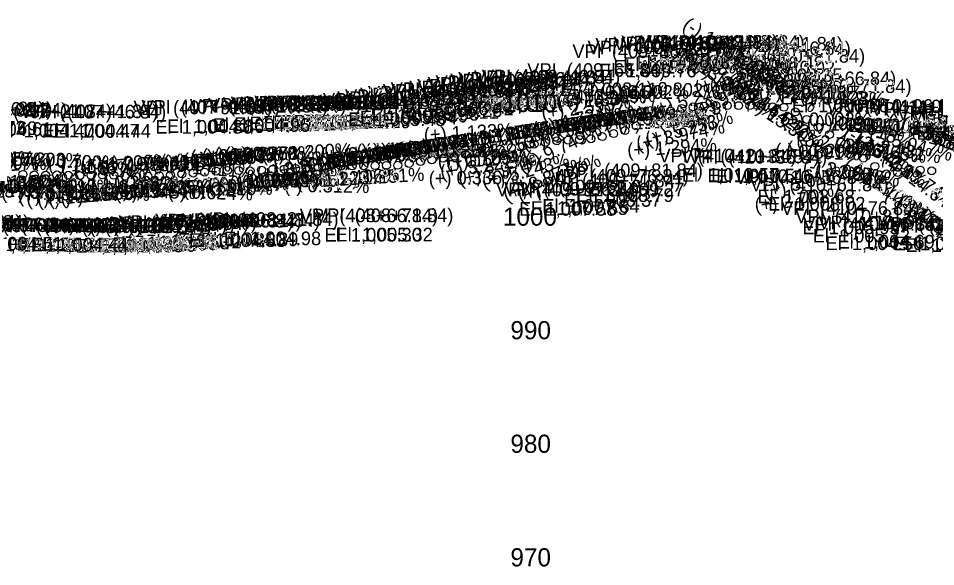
# Model space of a CAD drawing. Extents: x 16972137 to 16976972, y 12558490 to 12559551.
# Drawn here: x 16975097.7 to 16975501.5, y 12558789.2 to 12559030.6 of the extents above; entities that cross this region are included whole.
import ezdxf

# ---------------------------------------------------------------- set-up
doc = ezdxf.new("R2010")
doc.units = 0
for name, color, linetype in [('RD_DDB_ElevTX', 7, 'Continuous'), ('RD_DDB_GradeTX', 7, 'Continuous'), ('RD_DDB_PI', 7, 'Continuous')]:
    doc.layers.add(name, color=color, linetype=linetype)

msp = doc.modelspace()

# ---------------------------------------------------------------- linework, layer by layer
at = {"layer": 'RD_DDB_PI'}
for centre in [(16975399.74, 12558991.93), (16975404.74, 12558992.17), (16975409.74, 12558992.19), (16975414.74, 12558992.16), (16975419.74, 12558992.16), (16975424.74, 12558991.88), (16975379.74, 12558988.12), (16975384.74, 12558989.77), (16975389.74, 12558990.95), (16975394.74, 12558991.6), (16975429.74, 12558991.62), (16975434.74, 12558991.42), (16975439.74, 12558989.42), (16975374.74, 12558985.68), (16975444.74, 12558986.08), (16975359.74, 12558979.85), (16975364.74, 12558981.16), (16975369.74, 12558983.25), (16975449.74, 12558982.72), (16975329.74, 12558975.94), (16975334.74, 12558976.66), (16975339.74, 12558976.94), (16975344.74, 12558977.21), (16975349.74, 12558977.54), (16975354.74, 12558978.53), (16975454.74, 12558979.44), (16975459.74, 12558976.17), (16975304.74, 12558972.17), (16975309.74, 12558972.94), (16975314.74, 12558973.7), (16975319.74, 12558974.45), (16975324.74, 12558975.2), (16975464.74, 12558972.74), (16975274.74, 12558967.5), (16975279.74, 12558968.29), (16975284.74, 12558969.08), (16975289.74, 12558969.86), (16975294.74, 12558970.63), (16975299.74, 12558971.41), (16975469.74, 12558969.07), (16975189.74, 12558963.63), (16975194.74, 12558963.55), (16975199.74, 12558963.47), (16975204.74, 12558963.78), (16975209.74, 12558964.13), (16975214.74, 12558964.23), (16975219.74, 12558964.55), (16975224.74, 12558964.83), (16975229.74, 12558965.11), (16975234.74, 12558965.36), (16975239.74, 12558965.51), (16975244.74, 12558965.61), (16975249.74, 12558965.68), (16975254.74, 12558965.75), (16975259.74, 12558965.82), (16975264.74, 12558965.9), (16975269.74, 12558966.7), (16975474.74, 12558965.41), (16975489.74, 12558964.02), (16975494.74, 12558963.79), (16975499.74, 12558963.47), (16975099.74, 12558961.88), (16975104.74, 12558961.64), (16975109.74, 12558961.56), (16975114.74, 12558961.68), (16975119.74, 12558961.53), (16975124.74, 12558961.39), (16975129.74, 12558961.5), (16975134.74, 12558961.65), (16975139.74, 12558961.51), (16975144.74, 12558961.16), (16975149.74, 12558961), (16975154.74, 12558961.08), (16975159.74, 12558961.31), (16975164.74, 12558961.66), (16975169.74, 12558962.07), (16975174.74, 12558962.48), (16975179.74, 12558962.9), (16975184.74, 12558963.33), (16975479.74, 12558962.09), (16975484.74, 12558962.76)]:
    msp.add_circle(centre, 1.75, dxfattribs=at)

# ---------------------------------------------------------------- texts
at = {"layer": 'RD_DDB_ElevTX'}
for s, p in [('1010', (16975311.02, 12558989.31)), ('1000', (16975311.02, 12558939.31)), ('990', (16975314.32, 12558889.31)), ('980', (16975314.32, 12558839.31)), ('970', (16975314.32, 12558789.31))]:
    msp.add_text(s, height=8, dxfattribs=at).set_placement(p)
at = {"layer": 'RD_DDB_GradeTX'}
for s, rotation, p in [('(-) 13.342%', 326.2932, (16975389.68, 12559026.42)), ('(-) 8.018%', 338.1532, (16975381.13, 12559016.15)), ('(-) 13.063%', 326.8491, (16975404.49, 12559015.84)), ('(-) 13.453%', 326.0724, (16975388.24, 12559013.24)), ('(+) 6.582%', 18.2168, (16975396.62, 12558996.84)), ('(-) 13.741%', 325.5091, (16975412.28, 12559012.42)), ('(-) 13.124%', 326.7268, (16975394.42, 12559008.25)), ('(+) 4.734%', 13.3166, (16975402.77, 12558997.12)), ('(+) 9.749%', 25.9875, (16975396.34, 12558986.2)), ('(+) 2.593%', 7.3885, (16975407.67, 12558996.3)), ('(-) 14.642%', 323.7924, (16975410.07, 12559001.6)), ('(-) 0.802%', 357.7037, (16975368.67, 12558997.07)), ('(+) 5.243%', 14.6898, (16975376.84, 12558987.43)), ('(+) 9.735%', 25.955, (16975390.76, 12558983.47)), ('(+) 1.334%', 3.8169, (16975414.67, 12558995.94)), ('(-) 14.642%', 323.7924, (16975415.07, 12558997.94)), ('(+) 0.965%', 2.763, (16975418.69, 12558995.85)), ('(+) 0.065%', 0.1852, (16975423.73, 12558995.23)), ('(+) 1.334%', 3.8169, (16975334.86, 12558990.61)), ('(+) 0.965%', 2.763, (16975338.79, 12558991.99)), ('(+) 0.065%', 0.1852, (16975343.73, 12558994.98)), ('(+) 0.002%', 0.0061, (16975353.5, 12558995.15)), ('(+) 8.377%', 22.7269, (16975386.01, 12558980.31)), ('(-) 0.118%', 359.6608, (16975432.06, 12558995.06)), ('(-) 1.123%', 356.7861, (16975441.65, 12558993.94)), ('(+) 2.593%', 7.3885, (16975328.37, 12558986.02)), ('(-) 13.305%', 326.3658, (16975417.98, 12558992.36)), ('(+) 6.582%', 18.2168, (16975320.88, 12558971.91)), ('(+) 3.053%', 8.6796, (16975322.37, 12558977.9)), ('(+) 4.734%', 13.3166, (16975325.05, 12558978.72)), ('(+) 3.035%', 8.6293, (16975327.37, 12558978.65)), ('(+) 3.017%', 8.5788, (16975334.71, 12558979.74)), ('(+) 2.999%', 8.5278, (16975338.2, 12558980.25)), ('(+) 2.973%', 8.4553, (16975342.97, 12558980.94)), ('(+) 2.844%', 8.0934, (16975348.13, 12558981.59)), ('(-) 0.118%', 359.6608, (16975351.99, 12558983.53)), ('(-) 1.123%', 356.7861, (16975361.11, 12558986.44)), ('(-) 1.036%', 357.0359, (16975364.83, 12558985.97)), ('(+) 5.253%', 14.7169, (16975374.66, 12558974.46)), ('(+) 0.002%', 0.0061, (16975433.5, 12558983.16)), ('(-) 8.018%', 338.1532, (16975455.02, 12558986.52)), ('(-) 8.555%', 336.8409, (16975479.91, 12558984.55)), ('(+) 3.165%', 8.9932, (16975294.38, 12558973.65)), ('(+) 3.141%', 8.9248, (16975301.13, 12558974.69)), ('(+) 3.124%', 8.8765, (16975304.27, 12558975.16)), ('(+) 3.106%', 8.8279, (16975309.51, 12558975.96)), ('(+) 3.089%', 8.7788, (16975312.88, 12558976.47)), ('(+) 3.071%', 8.7294, (16975319.7, 12558977.51)), ('(+) 1.133%', 3.2426, (16975356.25, 12558980.88)), ('(+) 1.105%', 3.1627, (16975361.73, 12558981.16)), ('(+) 3.974%', 11.2377, (16975370.36, 12558972.46)), ('(-) 1.036%', 357.0359, (16975444.72, 12558981.83)), ('(-) 0.802%', 357.7037, (16975448.13, 12558981.88)), ('(-) 13.342%', 326.2932, (16975455.39, 12558982.58)), ('(-) 8.686%', 336.5257, (16975485.61, 12558982.47)), ('(+) 2.844%', 8.0934, (16975268.97, 12558970.33)), ('(+) 1.133%', 3.2426, (16975276.39, 12558976.35)), ('(+) 3.185%', 9.0495, (16975289.25, 12558972.85)), ('(+) 9.749%', 25.9875, (16975319.68, 12558962.18)), ('(-) 13.453%', 326.0724, (16975460.46, 12558979.12)), ('(-) 5.047%', 345.8371, (16975471.76, 12558976.82)), ('(-) 8.686%', 336.5257, (16975490.61, 12558980.3)), ('(-) 9.687%', 334.1562, (16975497.12, 12558980.17)), ('(+) 3.053%', 8.6796, (16975243.34, 12558965.84)), ('(+) 3.035%', 8.6293, (16975248.33, 12558966.65)), ('(+) 3.017%', 8.5788, (16975255.66, 12558967.82)), ('(+) 2.999%', 8.5278, (16975259.14, 12558968.4)), ('(+) 2.973%', 8.4553, (16975263.9, 12558969.19)), ('(+) 5.253%', 14.7169, (16975294.4, 12558965.78)), ('(+) 1.294%', 3.7033, (16975365.93, 12558969.57)), ('(-) 2.789%', 352.0614, (16975439.96, 12558974.84)), ('(-) 2.614%', 352.5549, (16975456.32, 12558971.95)), ('(-) 2.765%', 352.1274, (16975459.83, 12558971.95)), ('(-) 3.431%', 350.2663, (16975466.36, 12558973.01)), ('(+) 0.580%', 1.6608, (16975173.56, 12558966.59)), ('(+) 0.436%', 1.248, (16975178.63, 12558967.17)), ('(+) 0.277%', 0.7939, (16975184.06, 12558967.77)), ('(+) 0.268%', 0.7682, (16975188.58, 12558967.86)), ('(+) 1.200%', 3.4347, (16975204.94, 12558967.55)), ('(+) 3.141%', 8.9248, (16975222.16, 12558962.29)), ('(+) 3.124%', 8.8765, (16975225.29, 12558962.83)), ('(+) 3.106%', 8.8279, (16975230.52, 12558963.7)), ('(+) 0.414%', 1.1859, (16975230.56, 12558967.56)), ('(+) 3.089%', 8.7788, (16975233.88, 12558964.27)), ('(+) 3.071%', 8.7294, (16975240.68, 12558965.37)), ('(+) 1.139%', 3.2587, (16975241.66, 12558968.8)), ('(+) 1.105%', 3.1629, (16975246.73, 12558969.05)), ('(+) 1.006%', 2.8782, (16975250.33, 12558969.15)), ('(+) 0.580%', 1.6608, (16975253.52, 12558968.91)), ('(+) 0.436%', 1.248, (16975258.61, 12558968.92)), ('(+) 0.277%', 0.7939, (16975264.05, 12558968.88)), ('(+) 0.268%', 0.7682, (16975268.58, 12558968.94)), ('(+) 0.259%', 0.7426, (16975273.46, 12558968.99)), ('(-) 0.891%', 357.4484, (16975430.71, 12558969.65)), ('(-) 1.299%', 356.2842, (16975435.72, 12558970.63)), ('(+) 0.124%', 0.3549, (16975065.25, 12558965.9)), ('(-) 0.740%', 357.881, (16975069.25, 12558965.08)), ('(+) 0.617%', 1.766, (16975070.74, 12558962.68)), ('(-) 0.557%', 358.4036, (16975073.91, 12558966.35)), ('(-) 0.303%', 359.1328, (16975088.19, 12558965.8)), ('(-) 0.700%', 357.9941, (16975104.13, 12558965.24)), ('(-) 1.566%', 355.5233, (16975110.68, 12558964.11)), ('(-) 1.877%', 354.6387, (16975116.17, 12558963.35)), ('(+) 1.719%', 4.9123, (16975122.43, 12558960.99)), ('(+) 1.200%', 3.4347, (16975125.09, 12558962.76)), ('(-) 0.598%', 358.2878, (16975133.82, 12558964.11)), ('(+) 1.406%', 4.0225, (16975145.57, 12558962.63)), ('(-) 0.557%', 358.4036, (16975153.87, 12558964.12)), ('(+) 1.251%', 3.5806, (16975156.63, 12558963.6)), ('(+) 1.139%', 3.2587, (16975161.8, 12558964.25)), ('(+) 1.105%', 3.1629, (16975166.86, 12558964.64)), ('(+) 1.006%', 2.8782, (16975170.44, 12558965.13)), ('(+) 3.222%', 9.152, (16975203.11, 12558959.01)), ('(+) 3.185%', 9.0495, (16975210.31, 12558960.28)), ('(-) 0.313%', 359.1029, (16975209.84, 12558966.32)), ('(+) 3.165%', 8.9932, (16975215.42, 12558961.15)), ('(+) 1.105%', 3.1627, (16975282.52, 12558964.76)), ('(+) 3.222%', 9.152, (16975283.94, 12558959.88)), ('(+) 1.294%', 3.7033, (16975286.11, 12558964.4)), ('(+) 3.974%', 11.2377, (16975291.99, 12558956.89)), ('(+) 5.243%', 14.6898, (16975302.66, 12558955.58)), ('(+) 8.377%', 22.7269, (16975312.61, 12558949.56)), ('(+) 9.735%', 25.955, (16975319.33, 12558948.7)), ('(-) 13.741%', 325.5091, (16975477.34, 12558967.72)), ('(-) 1.411%', 355.9634, (16975163.97, 12558962.81)), ('(+) 5.018%', 14.0851, (16975426.48, 12558951.24)), ('(-) 3.065%', 351.2879, (16975442.84, 12558963.15)), ('(-) 2.846%', 351.9003, (16975448.13, 12558961.68)), ('(-) 13.124%', 326.7268, (16975460.49, 12558964.9)), ('(-) 13.063%', 326.8491, (16975464.09, 12558962.58)), ('(-) 14.642%', 323.7924, (16975480.75, 12558964.74)), ('(+) 0.832%', 2.3829, (16975078.56, 12558954.42)), ('(-) 1.411%', 355.9634, (16975083.33, 12558956.47)), ('(+) 0.904%', 2.589, (16975084.36, 12558954.73)), ('(-) 0.313%', 359.1029, (16975129.67, 12558955.57)), ('(-) 0.312%', 359.107, (16975134.73, 12558955.49)), ('(+) 1.409%', 4.0302, (16975181.21, 12558953.8)), ('(+) 1.639%', 4.6854, (16975186, 12558954.37)), ('(+) 1.652%', 4.7219, (16975190.83, 12558954.78)), ('(+) 0.259%', 0.7426, (16975193.62, 12558955.96)), ('(+) 1.665%', 4.758, (16975196.18, 12558955.24)), ('(+) 0.336%', 0.9625, (16975198.43, 12558955.78)), ('(+) 1.719%', 4.9123, (16975203.15, 12558955.88)), ('(+) 1.223%', 3.4983, (16975220.14, 12558955.7)), ('(+) 1.406%', 4.0225, (16975226.21, 12558956.27)), ('(+) 1.251%', 3.5806, (16975237.21, 12558956.62)), ('(+) 0.336%', 0.9625, (16975278.41, 12558957.13)), ('(+) 0.425%', 1.2186, (16975063.71, 12558951.09)), ('(+) 0.085%', 0.2447, (16975073.66, 12558953.7)), ('(-) 0.624%', 358.2125, (16975083.49, 12558954.07)), ('(+) 0.310%', 0.8881, (16975090.24, 12558951.08)), ('(-) 0.209%', 359.401, (16975093.52, 12558953.8)), ('(+) 0.911%', 2.6078, (16975097.64, 12558949.47)), ('(-) 0.115%', 359.6692, (16975101.87, 12558953.82)), ('(+) 1.652%', 4.7219, (16975111.11, 12558948.2)), ('(+) 1.665%', 4.758, (16975116.48, 12558948.6)), ('(-) 0.983%', 357.1871, (16975118.1, 12558951.97)), ('(-) 0.314%', 359.1012, (16975125.07, 12558952.32)), ('(+) 0.477%', 1.3674, (16975129.66, 12558953.03)), ('(-) 0.545%', 358.4399, (16975138.37, 12558952.02)), ('(+) 1.223%', 3.4983, (16975140.29, 12558950.82)), ('(+) 0.425%', 1.2186, (16975143.69, 12558952.79)), ('(+) 0.414%', 1.1859, (16975150.83, 12558953.91)), ('(+) 0.617%', 1.766, (16975151.07, 12558953.15)), ('(-) 0.624%', 358.2125, (16975163.45, 12558951.57)), ('(+) 0.310%', 0.8881, (16975170.23, 12558952.32)), ('(+) 0.911%', 2.6078, (16975177.55, 12558953.11)), ('(-) 0.312%', 359.107, (16975214.72, 12558954.24)), ('(+) 1.409%', 4.0302, (16975101.42, 12558948.18)), ('(+) 1.639%', 4.6854, (16975106.28, 12558947.84)), ('(+) 2.701%', 7.6924, (16975422.23, 12558945.24)), ('(-) 14.642%', 323.7924, (16975478.66, 12558951.39)), ('(-) 13.305%', 326.3658, (16975483.75, 12558948.61))]:
    msp.add_text(s, height=6, rotation=rotation, dxfattribs=at).set_placement(p)
at = {"layer": 'RD_DDB_PI'}
for s, p in [('VPI  (409+96.84)', (16975351.74, 12559015.95)), ('VPI  (410+01.84)', (16975359.69, 12559016.6)), ('VPI  (410+06.84)', (16975363.16, 12559016.93)), ('VPI  (410+11.84)', (16975371.35, 12559017.17)), ('VPI  (410+16.84)', (16975374.81, 12559017.19)), ('VPI  (410+26.84)', (16975382.92, 12559017.16)), ('VPI  (410+41.84)', (16975399.81, 12559016.42)), ('VPI  (409+86.84)', (16975341.62, 12559013.12)), ('VPI  (409+91.84)', (16975348.27, 12559014.77)), ('VPI  (410+46.84)', (16975403.27, 12559014.42)), ('El  1,010.33', (16975364.02, 12559007.45)), ('El  1,010.46', (16975369.82, 12559008.1)), ('El  1,010.52', (16975374.26, 12559008.43)), ('El  1,010.57', (16975379.76, 12559008.67)), ('El  1,010.58', (16975384.5, 12559008.69)), ('El  1,010.57', (16975394.76, 12559008.66)), ('VPI  (410+51.84)', (16975409.57, 12559011.08)), ('El  1,010.42', (16975409.5, 12559007.92)), ('VPI  (409+66.84)', (16975321.74, 12559004.85)), ('El  1,009.76', (16975353.46, 12559004.62)), ('El  1,010.09', (16975359.7, 12559006.27)), ('El  1,010.02', (16975414.38, 12559005.92)), ('VPI  (409+26.84)', (16975281.39, 12558999.45)), ('VPI  (409+31.84)', (16975287.86, 12559000.2)), ('VPI  (409+36.84)', (16975291.33, 12559000.94)), ('VPI  (409+41.84)', (16975298.27, 12559001.66)), ('VPI  (409+46.84)', (16975301.74, 12559001.94)), ('El  1,009.35', (16975417.66, 12559002.58)), ('VPI  (410+66.84)', (16975423.27, 12559001.17)), ('VPI  (409+01.84)', (16975258.16, 12558995.63)), ('VPI  (409+06.84)', (16975261.62, 12558996.41)), ('VPI  (409+11.84)', (16975269.81, 12558997.17)), ('VPI  (409+16.84)', (16975273.27, 12558997.94)), ('VPI  (409+21.84)', (16975277.92, 12558998.7)), ('El  1,008.11', (16975336.24, 12558996.35)), ('VPI  (410+71.84)', (16975429.99, 12558997.74)), ('VPI  (408+76.84)', (16975231.8, 12558991.7)), ('VPI  (408+81.84)', (16975238.04, 12558992.5)), ('VPI  (408+86.84)', (16975241.5, 12558993.29)), ('VPI  (408+91.84)', (16975248.16, 12558994.08)), ('VPI  (408+96.84)', (16975251.62, 12558994.86)), ('El  1,007.18', (16975299.91, 12558991.7)), ('El  1,007.33', (16975302.66, 12558992.44)), ('El  1,007.47', (16975308.64, 12558993.16)), ('El  1,007.53', (16975312.84, 12558993.44)), ('El  1,007.37', (16975433.23, 12558992.67)), ('VPI  (406+91.84)', (16975048.27, 12558987.92)), ('VPI  (406+96.84)', (16975051.74, 12558987.74)), ('VPI  (407+01.84)', (16975058.33, 12558987.35)), ('VPI  (407+91.84)', (16975148.45, 12558988.33)), ('VPI  (407+96.84)', (16975151.92, 12558988.63)), ('VPI  (408+16.84)', (16975173.16, 12558989.13)), ('VPI  (408+26.84)', (16975181.27, 12558989.55)), ('VPI  (408+31.84)', (16975187.74, 12558989.83)), ('VPI  (408+36.84)', (16975191.21, 12558990.11)), ('VPI  (408+41.84)', (16975198.16, 12558990.36)), ('VPI  (408+46.84)', (16975201.62, 12558990.51)), ('VPI  (408+51.84)', (16975207.92, 12558990.61)), ('VPI  (408+56.84)', (16975211.39, 12558990.68)), ('VPI  (408+61.84)', (16975218.16, 12558990.75)), ('El  1,006.26', (16975267.93, 12558987.13)), ('El  1,006.42', (16975272.96, 12558987.91)), ('El  1,006.57', (16975278.23, 12558988.67)), ('El  1,006.73', (16975283.08, 12558989.44)), ('El  1,006.88', (16975288.08, 12558990.2)), ('El  1,007.03', (16975292.96, 12558990.95)), ('El  1,006.68', (16975438.2, 12558989.24)), ('VPI  (410+96.84)', (16975453.27, 12558989.02)), ('VPI  (411+01.84)', (16975461.35, 12558988.79)), ('VPI  (411+06.84)', (16975464.81, 12558988.47)), ('VPI  (411+11.84)', (16975473, 12558987.77)), ('VPI  (407+21.84)', (16975078.1, 12558986.68)), ('VPI  (407+41.84)', (16975098.45, 12558986.65)), ('VPI  (407+46.84)', (16975101.92, 12558986.51)), ('El  1,005.48', (16975242.96, 12558983.2)), ('El  1,005.64', (16975248.05, 12558984)), ('El  1,005.80', (16975252.81, 12558984.79)), ('El  1,005.95', (16975257.84, 12558985.58)), ('El  1,006.11', (16975266.36, 12558986.36)), ('VPI  (411+26.84)', (16975484.57, 12558985.64)), ('VPI  (411+31.84)', (16975491.05, 12558984.95)), ('VPI  (411+36.84)', (16975494.51, 12558984.09)), ('El  1,004.72', (16975058.14, 12558979.42)), ('El  1,004.69', (16975063.28, 12558979.24)), ('El  1,004.80', (16975158.05, 12558979.83)), ('El  1,004.86', (16975163.17, 12558980.13)), ('El  1,004.96', (16975183.28, 12558980.63)), ('El  1,005.05', (16975192.72, 12558981.05)), ('El  1,005.10', (16975199.47, 12558981.33)), ('El  1,005.16', (16975204.58, 12558981.61)), ('El  1,005.21', (16975209.23, 12558981.86)), ('El  1,005.24', (16975212.69, 12558982.01)), ('El  1,005.26', (16975217.69, 12558982.11)), ('El  1,005.27', (16975222.87, 12558982.18)), ('El  1,005.29', (16975227.69, 12558982.25)), ('El  1,004.94', (16975463.28, 12558980.52)), ('El  1,004.90', (16975468.17, 12558980.29)), ('El  1,004.83', (16975472.78, 12558979.97)), ('El  1,004.69', (16975478.28, 12558979.27)), ('El  1,004.61', (16975069.82, 12558978.85)), ('El  1,004.47', (16975088.46, 12558978.18)), ('El  1,004.47', (16975108.46, 12558978.15)), ('El  1,004.44', (16975113.28, 12558978.01)), ('El  1,004.27', (16975493.11, 12558977.14)), ('El  1,004.13', (16975499.44, 12558976.45)), ('VPI  (410+21.84)', (16975379.46, 12558967.16)), ('VPI  (410+31.84)', (16975389.4, 12558966.88)), ('VPI  (410+36.84)', (16975392.86, 12558966.62)), ('VPI  (409+81.84)', (16975338.16, 12558960.68)), ('VPI  (409+71.84)', (16975328.45, 12558956.16)), ('VPI  (409+76.84)', (16975331.92, 12558958.25)), ('El  1,010.57', (16975389.76, 12558958.66)), ('El  1,010.51', (16975401.12, 12558958.38)), ('El  1,010.46', (16975404.82, 12558958.12)), ('VPI  (410+56.84)', (16975413.04, 12558957.72)), ('VPI  (409+51.84)', (16975308.04, 12558952.21)), ('VPI  (409+56.84)', (16975311.5, 12558952.54)), ('VPI  (409+61.84)', (16975318.27, 12558953.53)), ('El  1,009.27', (16975348.11, 12558952.18)), ('VPI  (410+61.84)', (16975419.81, 12558954.44)), ('El  1,008.37', (16975337.93, 12558947.66)), ('El  1,008.79', (16975343.34, 12558949.75)), ('El  1,008.68', (16975423.08, 12558949.22)), ('El  1,007.58', (16975318.14, 12558943.71)), ('El  1,007.65', (16975323.26, 12558944.04)), ('El  1,007.84', (16975328.34, 12558945.03)), ('El  1,008.02', (16975427.72, 12558945.94)), ('VPI  (410+76.84)', (16975433.45, 12558944.07)), ('VPI  (408+11.84)', (16975169.69, 12558938.78)), ('VPI  (408+21.84)', (16975177.8, 12558939.23)), ('VPI  (408+66.84)', (16975221.62, 12558940.82)), ('VPI  (408+71.84)', (16975228.33, 12558940.9)), ('VPI  (410+81.84)', (16975439.69, 12558940.41)), ('VPI  (406+81.84)', (16975038.16, 12558938)), ('VPI  (406+86.84)', (16975041.62, 12558937.95)), ('VPI  (407+06.84)', (16975061.8, 12558936.88)), ('VPI  (407+11.84)', (16975069.99, 12558936.64)), ('VPI  (407+16.84)', (16975073.45, 12558936.56)), ('VPI  (407+26.84)', (16975081.56, 12558936.53)), ('VPI  (407+31.84)', (16975088.04, 12558936.39)), ('VPI  (407+36.84)', (16975091.5, 12558936.5)), ('VPI  (407+51.84)', (16975108.22, 12558936.16)), ('VPI  (407+56.84)', (16975111.68, 12558936)), ('VPI  (407+61.84)', (16975118.45, 12558936.08)), ('VPI  (407+66.84)', (16975121.92, 12558936.31)), ('VPI  (407+71.84)', (16975128.63, 12558936.66)), ('VPI  (407+76.84)', (16975132.09, 12558937.07)), ('VPI  (407+81.84)', (16975138.33, 12558937.48)), ('VPI  (407+86.84)', (16975141.8, 12558937.9)), ('VPI  (408+01.84)', (16975158.04, 12558938.55)), ('VPI  (408+06.84)', (16975161.5, 12558938.47)), ('VPI  (410+86.84)', (16975443.16, 12558937.09)), ('El  1,005.95', (16975442.84, 12558935.57)), ('VPI  (410+91.84)', (16975449.81, 12558937.76)), ('VPI  (411+16.84)', (16975476.46, 12558937.01)), ('VPI  (411+21.84)', (16975481.11, 12558936.3)), ('El  1,004.98', (16975188.2, 12558930.73)), ('El  1,005.30', (16975232.52, 12558932.32)), ('El  1,005.32', (16975237.31, 12558932.4)), ('El  1,005.22', (16975447.37, 12558931.91)), ('El  1,004.51', (16975074.58, 12558928.38)), ('El  1,004.46', (16975078.28, 12558928.14)), ('El  1,004.45', (16975083.08, 12558928.06)), ('El  1,004.44', (16975093.28, 12558928.03)), ('El  1,004.42', (16975097.96, 12558927.89)), ('El  1,004.44', (16975103.28, 12558928)), ('El  1,004.37', (16975118.05, 12558927.66)), ('El  1,004.34', (16975122.87, 12558927.5)), ('El  1,004.35', (16975127.66, 12558927.58)), ('El  1,004.40', (16975133.17, 12558927.81)), ('El  1,004.47', (16975138.46, 12558928.16)), ('El  1,004.55', (16975142.84, 12558928.57)), ('El  1,004.63', (16975147.9, 12558928.98)), ('El  1,004.72', (16975153.14, 12558929.4)), ('El  1,004.85', (16975167.96, 12558930.05)), ('El  1,004.83', (16975172.78, 12558929.97)), ('El  1,004.89', (16975178.17, 12558930.28)), ('El  1,004.56', (16975453.05, 12558928.59)), ('El  1,004.69', (16975458.28, 12558929.26)), ('El  1,004.54', (16975483.05, 12558928.51)), ('El  1,004.40', (16975488.17, 12558927.8))]:
    msp.add_text(s, height=6, dxfattribs=at).set_placement(p)

doc.saveas('drawing.dxf')
